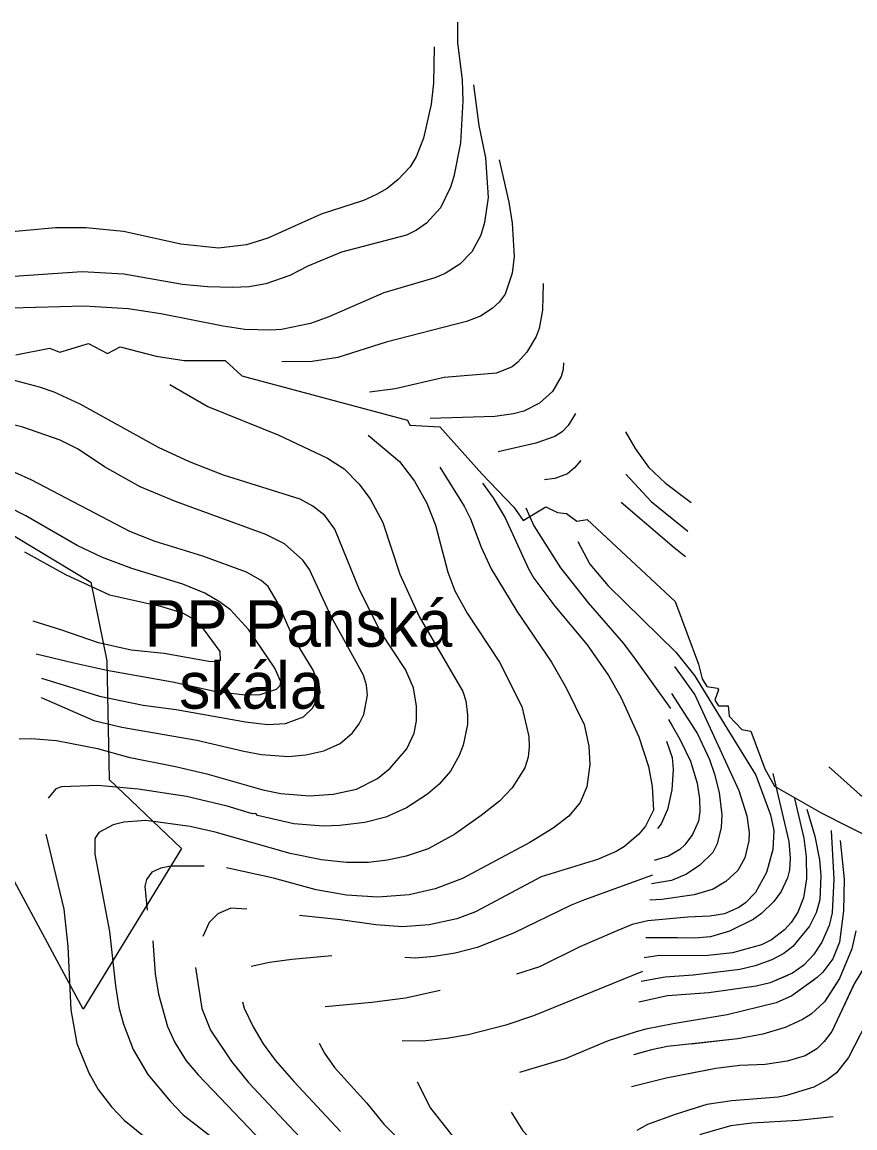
# Model space of a CAD drawing. Extents: x -1900516 to -575031, y -3809306 to -1157387.
# Drawn here: x -579489 to -579042, y -1158848 to -1158254 of the extents above; entities that cross this region are included whole.
import ezdxf

# ---------------------------------------------------------------- set-up
doc = ezdxf.new("R2010")
doc.units = 0
for name, color, linetype in [('01_SPRÁV_HRANICE', 7, 'Continuous'), ('01_VRSTEVNICE', 7, 'Continuous'), ('06_CHR_ÚZEMÍ', 7, 'Continuous')]:
    doc.layers.add(name, color=color, linetype=linetype)

msp = doc.modelspace()

# ---------------------------------------------------------------- linework, layer by layer
at = {"layer": '01_SPRÁV_HRANICE'}
for p, q in [((-579492.52, -1158432.42), (-579474.34, -1158428.74)), ((-579492.52, -1158432.42), (-579474.34, -1158428.74)), ((-579474.34, -1158428.74), (-579468.76, -1158430.87)), ((-579474.34, -1158428.74), (-579468.76, -1158430.87)), ((-579468.76, -1158430.87), (-579453.44, -1158426.35)), ((-579468.76, -1158430.87), (-579453.44, -1158426.35)), ((-579453.44, -1158426.35), (-579443.27, -1158431.59)), ((-579453.44, -1158426.35), (-579443.27, -1158431.59)), ((-579443.27, -1158431.59), (-579436.46, -1158428.12)), ((-579443.27, -1158431.59), (-579436.46, -1158428.12)), ((-579436.46, -1158428.12), (-579417.04, -1158433.06)), ((-579436.46, -1158428.12), (-579417.04, -1158433.06)), ((-579417.04, -1158433.06), (-579402.05, -1158435.39)), ((-579417.04, -1158433.06), (-579402.05, -1158435.39)), ((-579402.05, -1158435.39), (-579380.03, -1158435.41)), ((-579402.05, -1158435.39), (-579380.03, -1158435.41)), ((-579380.03, -1158435.41), (-579370.96, -1158443.7)), ((-579380.03, -1158435.41), (-579370.96, -1158443.7)), ((-579370.96, -1158443.7), (-579282.01, -1158467.49)), ((-579370.96, -1158443.7), (-579282.01, -1158467.49)), ((-579282.01, -1158467.49), (-579280.84, -1158470.22)), ((-579282.01, -1158467.49), (-579280.84, -1158470.22)), ((-579280.84, -1158470.22), (-579264.65, -1158471.08)), ((-579280.84, -1158470.22), (-579264.65, -1158471.08)), ((-579264.65, -1158471.08), (-579242.12, -1158496.25)), ((-579264.65, -1158471.08), (-579242.12, -1158496.25)), ((-579242.12, -1158496.25), (-579224.83, -1158514.13)), ((-579242.12, -1158496.25), (-579224.83, -1158514.13)), ((-579224.83, -1158514.13), (-579219.83, -1158521.43)), ((-579224.83, -1158514.13), (-579219.83, -1158521.43)), ((-579219.83, -1158521.43), (-579207.65, -1158514.05)), ((-579219.83, -1158521.43), (-579207.65, -1158514.05)), ((-579207.65, -1158514.05), (-579201.49, -1158517.14)), ((-579207.65, -1158514.05), (-579201.49, -1158517.14)), ((-579201.49, -1158517.14), (-579196.53, -1158517.67)), ((-579201.49, -1158517.14), (-579196.53, -1158517.67)), ((-579196.53, -1158517.67), (-579191.1, -1158521.77)), ((-579196.53, -1158517.67), (-579191.1, -1158521.77)), ((-579191.1, -1158521.77), (-579185.48, -1158520.78)), ((-579191.1, -1158521.77), (-579185.48, -1158520.78)), ((-579185.48, -1158520.78), (-579138.21, -1158564.86)), ((-579185.48, -1158520.78), (-579138.21, -1158564.86)), ((-579138.21, -1158564.86), (-579125.72, -1158598.51)), ((-579138.21, -1158564.86), (-579125.72, -1158598.51)), ((-579125.72, -1158598.51), (-579123.73, -1158606.52)), ((-579125.72, -1158598.51), (-579123.73, -1158606.52)), ((-579123.73, -1158606.52), (-579121.23, -1158610.56)), ((-579123.73, -1158606.52), (-579121.23, -1158610.56)), ((-579121.23, -1158610.56), (-579115.4, -1158611.53)), ((-579121.23, -1158610.56), (-579115.4, -1158611.53)), ((-579114.88, -1158612.44), (-579116.81, -1158617.88)), ((-579114.88, -1158612.44), (-579116.81, -1158617.88)), ((-579115.4, -1158611.53), (-579114.88, -1158612.44)), ((-579115.4, -1158611.53), (-579114.88, -1158612.44)), ((-579116.81, -1158617.88), (-579115, -1158620.98)), ((-579116.81, -1158617.88), (-579115, -1158620.98)), ((-579115, -1158620.98), (-579109.76, -1158620.86)), ((-579115, -1158620.98), (-579109.76, -1158620.86)), ((-579109.76, -1158620.86), (-579109.15, -1158626.56)), ((-579109.76, -1158620.86), (-579109.15, -1158626.56)), ((-579109.15, -1158626.56), (-579102.35, -1158633.68)), ((-579109.15, -1158626.56), (-579102.35, -1158633.68)), ((-579102.35, -1158633.68), (-579097.52, -1158634.56)), ((-579102.35, -1158633.68), (-579097.52, -1158634.56)), ((-579097.52, -1158634.56), (-579090.03, -1158654.79)), ((-579097.52, -1158634.56), (-579090.03, -1158654.79)), ((-579090.03, -1158654.79), (-579084.84, -1158664.04)), ((-579090.03, -1158654.79), (-579084.84, -1158664.04)), ((-579084.84, -1158664.04), (-579059.76, -1158678.42)), ((-579084.84, -1158664.04), (-579059.76, -1158678.42)), ((-579059.76, -1158678.42), (-579030.73, -1158693.13)), ((-579059.76, -1158678.42), (-579030.73, -1158693.13))]:
    msp.add_line(p, q, dxfattribs=at)
at = {"layer": '01_VRSTEVNICE'}
for p, q in [((-579267.78, -1158267), (-579268.06, -1158286.47)), ((-579268.06, -1158286.47), (-579269.32, -1158297.68)), ((-579269.32, -1158297.68), (-579273.38, -1158315.9)), ((-579273.38, -1158315.9), (-579277.31, -1158325.99)), ((-579277.31, -1158325.99), (-579280.67, -1158331.31)), ((-579280.67, -1158331.31), (-579287.11, -1158338.18)), ((-579293, -1158342.94), (-579298.6, -1158346.31)), ((-579287.11, -1158338.18), (-579293, -1158342.94)), ((-579298.6, -1158346.31), (-579305.75, -1158349.39)), ((-579305.75, -1158349.39), (-579328.45, -1158356.82)), ((-579328.45, -1158356.82), (-579357.04, -1158369.71)), ((-579471.1, -1158364.1), (-579509.78, -1158367.75)), ((-579454.85, -1158364.1), (-579471.1, -1158364.1)), ((-579434.67, -1158366.21), (-579454.85, -1158364.1)), ((-579403.84, -1158372.93), (-579434.67, -1158366.21)), ((-579357.04, -1158369.71), (-579368.53, -1158373.35)), ((-579383.66, -1158375.03), (-579403.84, -1158372.93)), ((-579368.53, -1158373.35), (-579383.66, -1158375.03))]:
    msp.add_line(p, q, dxfattribs=at)
for points in [[(-579255.17, -1158253.64), (-579255.17, -1158264.66), (-579252.64, -1158284.79), (-579252.36, -1158296), (-579253.62, -1158318.42), (-579257.13, -1158336.64), (-579258.95, -1158342.24), (-579264.27, -1158353.45), (-579271.84, -1158361.58), (-579277.17, -1158365.36), (-579282.49, -1158368.03), (-579317.45, -1158377.17), (-579335.59, -1158384.81), (-579345.22, -1158389.73), (-579358.16, -1158394.23), (-579367.13, -1158395.77), (-579376.09, -1158396.19), (-579389.55, -1158395.77), (-579403, -1158394.51), (-579434.39, -1158389.05), (-579456.81, -1158387.78), (-579501.65, -1158390.87)], [(-579246.57, -1158287.28), (-579243.68, -1158309.17), (-579240.17, -1158326.55), (-579238.63, -1158347.85), (-579240.59, -1158361.3), (-579242.69, -1158368.03), (-579247.46, -1158377), (-579253.91, -1158383.72), (-579261.75, -1158388.77), (-579267.36, -1158391.01), (-579294.82, -1158399), (-579324.25, -1158411.89), (-579334.06, -1158415.53), (-579349.75, -1158418.75), (-579355.64, -1158419.17), (-579369.37, -1158418.75), (-579381.14, -1158417.07), (-579414.49, -1158410.34), (-579432.15, -1158407.68), (-579455.69, -1158406.28), (-579494.92, -1158407.26), (-579522.39, -1158405.02), (-579542.01, -1158401.8), (-579571.56, -1158397.99)], [(-579232.69, -1158327.64), (-579227.56, -1158350.37), (-579225.74, -1158361.58), (-579224.76, -1158379.52), (-579225.74, -1158388.49), (-579229.52, -1158399.83), (-579232.75, -1158404.04), (-579236.53, -1158407.4), (-579242.83, -1158411.61), (-579250.26, -1158414.55), (-579293.42, -1158425.62), (-579319.48, -1158433.89), (-579333.22, -1158435.99), (-579349.58, -1158436.13)], [(-579209.15, -1158393.99), (-579209.48, -1158408.38), (-579211.31, -1158418.19), (-579212.85, -1158422.54), (-579217.89, -1158430.94), (-579222.66, -1158436.41), (-579225.74, -1158438.79), (-579234.29, -1158442.29), (-579262.31, -1158444.54), (-579288.66, -1158450.7), (-579302.47, -1158452.46)], [(-579198.19, -1158436.68), (-579198.35, -1158440.35), (-579199.4, -1158443.98), (-579204.16, -1158452.1), (-579211.03, -1158458.27), (-579219.57, -1158462.61), (-579225.04, -1158464.15), (-579235.13, -1158465.55), (-579269.85, -1158466.56)], [(-579490.72, -1158638.75), (-579483.99, -1158638.47), (-579470.54, -1158639.59), (-579448.68, -1158643.79), (-579431.86, -1158648.56), (-579406.64, -1158653.46), (-579389.83, -1158657.53), (-579359.84, -1158666.07), (-579350.03, -1158668.04), (-579334.62, -1158669.3), (-579322.01, -1158668.46), (-579309.4, -1158665.66), (-579298.19, -1158660.05), (-579291.32, -1158654.45), (-579282.35, -1158644.08), (-579278.43, -1158635.67), (-579277.17, -1158628.94), (-579277.17, -1158621.09), (-579278.85, -1158611.29), (-579283.05, -1158601.48), (-579296.36, -1158581.3), (-579307.85, -1158558.6), (-579321.03, -1158525.95), (-579326.49, -1158518.66), (-579332.94, -1158513.76), (-579339.66, -1158509.98), (-579380.86, -1158496.94), (-579399.08, -1158489.8), (-579415.89, -1158482.09), (-579457.93, -1158458.97), (-579471.94, -1158452.52), (-579479.79, -1158449.72), (-579493.24, -1158446.22)], [(-579409.7, -1158448.39), (-579389.27, -1158460.09), (-579351.15, -1158475.5), (-579325.09, -1158487.98), (-579316.12, -1158493.58), (-579308.13, -1158501.71), (-579302.11, -1158509.83), (-579295.24, -1158522.45), (-579286.13, -1158550.19), (-579275.77, -1158572.89), (-579252.22, -1158613.25), (-579250.68, -1158618.29), (-579249.7, -1158625.86), (-579249.84, -1158630.9), (-579252.08, -1158642.11), (-579254.19, -1158647.72), (-579258.95, -1158656.13), (-579264.97, -1158662.99), (-579271.28, -1158668.46), (-579282.49, -1158675.74), (-579293.7, -1158680.79), (-579304.91, -1158683.59), (-579318.36, -1158685.27), (-579327.33, -1158685.55), (-579343.03, -1158684.29), (-579362.64, -1158679.81), (-579363.48, -1158678.83), (-579365.31, -1158678.97), (-579378.9, -1158674.9), (-579400.76, -1158669.72), (-579426.82, -1158665.79), (-579448.4, -1158663.69), (-579468.02, -1158664.39), (-579470.96, -1158665.52), (-579475.02, -1158670.56)], [(-579478.81, -1158616.47), (-579450.64, -1158628.8), (-579435.51, -1158632.45), (-579395.15, -1158639.31), (-579369.93, -1158645.34), (-579360.4, -1158647.02), (-579346.11, -1158648.14), (-579336.58, -1158647.3), (-579327.05, -1158645.2), (-579318.22, -1158641.13), (-579311.5, -1158635.39), (-579307.99, -1158630.62), (-579305.47, -1158625.58), (-579303.51, -1158615.21), (-579304.07, -1158609.89), (-579305.61, -1158604.56), (-579322.99, -1158572.89), (-579334.76, -1158547.67), (-579338.26, -1158542.62), (-579348.07, -1158533.94), (-579358.16, -1158528.89), (-579406.64, -1158511.24), (-579425.7, -1158503.25), (-579444.76, -1158492.6), (-579459.05, -1158483.07), (-579468.58, -1158478.17), (-579488.76, -1158471.3), (-579519.02, -1158463.87)], [(-579191.7, -1158463.81), (-579195.75, -1158470.32), (-579198.98, -1158473.68), (-579202.9, -1158476.34), (-579212.99, -1158479.85), (-579233.23, -1158484.51)], [(-579164.88, -1158473.8), (-579159.74, -1158482.65), (-579152.45, -1158492.74), (-579143.48, -1158501.29), (-579129.58, -1158511.7)], [(-579303.15, -1158475.59), (-579286.41, -1158489.66), (-579278.29, -1158500.17), (-579271.56, -1158512.08), (-579266.94, -1158523.85), (-579260.35, -1158549.07), (-579256.57, -1158559.16), (-579249.98, -1158571.21), (-579232.6, -1158597.55), (-579220.56, -1158621.38), (-579216.91, -1158637.35), (-579216.63, -1158642.96), (-579217.19, -1158648.56), (-579219.01, -1158654.17), (-579225.74, -1158664.95), (-579232.6, -1158672.1), (-579242.41, -1158679.95), (-579256.57, -1158689.9), (-579271, -1158697.74), (-579282.77, -1158701.67), (-579292.86, -1158703.91), (-579302.95, -1158705.03), (-579314.72, -1158705.17), (-579328.17, -1158703.77), (-579344.99, -1158700.27), (-579385.34, -1158688.78), (-579398.8, -1158685.69), (-579422.62, -1158682.61), (-579434.39, -1158683.45), (-579440.27, -1158684.85), (-579447.84, -1158689.06), (-579450.08, -1158692.28), (-579450.08, -1158700.69), (-579442.09, -1158742.16), (-579439.01, -1158771.31), (-579437.05, -1158782.8), (-579434.67, -1158792.05), (-579429.48, -1158805.5), (-579421.64, -1158818.95), (-579409.58, -1158833.39), (-579402.51, -1158840.62)], [(-579478.6, -1158606.12), (-579461.29, -1158611.43), (-579447.56, -1158615.77), (-579424.02, -1158620.67), (-579406.36, -1158622.92), (-579369.09, -1158629.5), (-579357.32, -1158631.04), (-579347.51, -1158630.48), (-579337.84, -1158626.84), (-579332.94, -1158621.94), (-579328.87, -1158613.81), (-579329.29, -1158610.73), (-579332.8, -1158601.76), (-579343.58, -1158583.82), (-579351.57, -1158565.89), (-579356.9, -1158556.92), (-579360.68, -1158553.55), (-579368.53, -1158549.21), (-579392.07, -1158540.52), (-579417.57, -1158532.68), (-579431.31, -1158527.35), (-579484.27, -1158499.47), (-579501.93, -1158491.62)], [(-579188.86, -1158489.06), (-579192.25, -1158493.02), (-579196.03, -1158496.24), (-579202.9, -1158498.9), (-579208.43, -1158499.52)], [(-579264.7, -1158492.74), (-579251.52, -1158513.76), (-579248.16, -1158520.48), (-579242.41, -1158535.62), (-579237.09, -1158547.39), (-579223.36, -1158570.09), (-579204.72, -1158597.55), (-579196.73, -1158611.29), (-579187.06, -1158630.9), (-579184.54, -1158642.68), (-579184.12, -1158652.48), (-579185.66, -1158664.53), (-579189.17, -1158672.94), (-579195.33, -1158680.23), (-579203.74, -1158686.67), (-579216.35, -1158694.38), (-579252.5, -1158713.72), (-579267.08, -1158719.32), (-579281.09, -1158722.41), (-579297.91, -1158723.81), (-579314.72, -1158722.69), (-579331.11, -1158719.74), (-579353.95, -1158713.58), (-579379.32, -1158707.97)], [(-579164.79, -1158496.43), (-579151.05, -1158511.1), (-579131.38, -1158527.13)], [(-579241.78, -1158501.41), (-579235.93, -1158509.26), (-579229.52, -1158519.92), (-579217.05, -1158547.39), (-579214.11, -1158552.43), (-579202.9, -1158567.43), (-579185.52, -1158588.17), (-579174.03, -1158604.7), (-579167.45, -1158616.33), (-579157.78, -1158637.63), (-579152.59, -1158653.6), (-579150.49, -1158664.25), (-579149.93, -1158677.01), (-579154.14, -1158685.55), (-579157.78, -1158689.9), (-579165.48, -1158696.48), (-579169.83, -1158699.15), (-579179.92, -1158703.49), (-579210.19, -1158712.88), (-579245.5, -1158731.66), (-579255.59, -1158735.44), (-579270.44, -1158738.66), (-579284.73, -1158739.64), (-579299.03, -1158738.66), (-579318.08, -1158735.86), (-579340.08, -1158733.62)], [(-579481.61, -1158593.07), (-579461.29, -1158597.83), (-579443.64, -1158601.76), (-579408.32, -1158608.06), (-579384.78, -1158613.25), (-579369.09, -1158615.07), (-579361.24, -1158614.79), (-579352.41, -1158611.99), (-579350.45, -1158610.03), (-579350.03, -1158608.06), (-579353.25, -1158600.64), (-579367.27, -1158580.04), (-579377.22, -1158569.39), (-579383.1, -1158565.04), (-579390.95, -1158560.42), (-579402.72, -1158555.66), (-579430.18, -1158547.11), (-579445.88, -1158541.22), (-579459.61, -1158534.78), (-579487.08, -1158518.8), (-579506.69, -1158508.99)], [(-579218.52, -1158514.53), (-579214.11, -1158524.27), (-579199.82, -1158546.83), (-579184.96, -1158565.6), (-579166.05, -1158587.47), (-579159.74, -1158595.87), (-579140.77, -1158622.45)], [(-579167.25, -1158511.59), (-579138.72, -1158535.9), (-579132.68, -1158540.77)], [(-579190.49, -1158532.73), (-579183.98, -1158544.87), (-579174.17, -1158556.5), (-579137.93, -1158592.03)], [(-579487.78, -1158538.14), (-579465.78, -1158550.47), (-579442.23, -1158561.26), (-579414.77, -1158567.43), (-579403, -1158570.93), (-579397.11, -1158574.15), (-579391.79, -1158579.62), (-579382.82, -1158591.67), (-579382.61, -1158596.51), (-579384.78, -1158597.35), (-579388.71, -1158597.13), (-579412.81, -1158592.79), (-579430.46, -1158591.11), (-579448.12, -1158587.04), (-579467.74, -1158580.32), (-579483.15, -1158575.55)], [(-579137.93, -1158592.03), (-579127.86, -1158604.62), (-579110.36, -1158632.87), (-579094.84, -1158658.27), (-579086.94, -1158679.43), (-579085.25, -1158687.9), (-579085.81, -1158698.06), (-579089.06, -1158710.47), (-579095.12, -1158721.2), (-579100.34, -1158726.7), (-579104.01, -1158729.24), (-579111.63, -1158732.62), (-579119.53, -1158733.89), (-579131.39, -1158734.46), (-579152.93, -1158736.45)], [(-579138.62, -1158599.86), (-579127.58, -1158615.09), (-579104.01, -1158666.45), (-579099.64, -1158680), (-579098.51, -1158689.03), (-579098.65, -1158693.54), (-579100.77, -1158702.57), (-579104.58, -1158709.34), (-579110.93, -1158715.41), (-579117.84, -1158719.36), (-579128, -1158722.47), (-579145.35, -1158725.01), (-579151.78, -1158725.35)], [(-579140.17, -1158614.3), (-579126.16, -1158635.98), (-579119.82, -1158649.8), (-579116.99, -1158657.7), (-579114.59, -1158667.58), (-579113.18, -1158679.43), (-579113.47, -1158686.34), (-579115.72, -1158695.09), (-579117.98, -1158699.75), (-579124.89, -1158706.52), (-579132.09, -1158711.32), (-579140.13, -1158714.71), (-579150.84, -1158716.57)], [(-579141.72, -1158628.26), (-579139.85, -1158631.74), (-579135.62, -1158638.8), (-579129.97, -1158650.65), (-579126.31, -1158662.5), (-579125.04, -1158670.97), (-579124.89, -1158677.74), (-579125.74, -1158682.96), (-579128.84, -1158690.16), (-579132.94, -1158695.66), (-579135.62, -1158698.06), (-579141.83, -1158701.73), (-579149.53, -1158704.09)], [(-579142.92, -1158640.01), (-579139.83, -1158648.68), (-579139.29, -1158655.16), (-579139.99, -1158666.03), (-579142.39, -1158676.61), (-579145.64, -1158684.37), (-579147.77, -1158686.88)], [(-579085.69, -1158657.26), (-579077.2, -1158693.82), (-579076.5, -1158702.71), (-579076.78, -1158709.06), (-579077.77, -1158713.29), (-579081.3, -1158720.77), (-579085.25, -1158726.13), (-579091.74, -1158732.48), (-579096.25, -1158735.73), (-579109.09, -1158742.08), (-579119.25, -1158745.04), (-579127.72, -1158745.75), (-579137.03, -1158745.6), (-579154, -1158745.67)], [(-579055.62, -1158653.75), (-579050.96, -1158657.84), (-579038.83, -1158668.71), (-579026.13, -1158676.33), (-579015.97, -1158680.84), (-579000.73, -1158685.07), (-578978.72, -1158688.6), (-578953.33, -1158694.1), (-578912.69, -1158708.36), (-578866.41, -1158720.91), (-578858.94, -1158723.74)], [(-579074.05, -1158670.71), (-579069.02, -1158692.13), (-579067.75, -1158702.01), (-579067.61, -1158713.86), (-579069.3, -1158724.02), (-579072.27, -1158731.78), (-579075.94, -1158737.42), (-579079.46, -1158741.23), (-579086.52, -1158746.73), (-579091.88, -1158749.27), (-579107.4, -1158753.65), (-579122.35, -1158755.2), (-579146.64, -1158755.16), (-579154.85, -1158756.29)], [(-579067.49, -1158676.5), (-579063.24, -1158691), (-579060.7, -1158703.7), (-579059.85, -1158712.17), (-579060.42, -1158725.15), (-579062.39, -1158732.2), (-579066.06, -1158739.26), (-579074.95, -1158750.26), (-579079.74, -1158754.07), (-579086.23, -1158757.46), (-579095.27, -1158760.56), (-579103.45, -1158762.53), (-579128.56, -1158765.64), (-579143.53, -1158766.77), (-579156.54, -1158769.03)], [(-579476.43, -1158689.9), (-579466.62, -1158730.25), (-579464.51, -1158750.29), (-579462.97, -1158784.2), (-579459.75, -1158802.42), (-579453.3, -1158818.11), (-579448.26, -1158827.08), (-579441.1, -1158836.33)], [(-579049.54, -1158693.33), (-579047.44, -1158714.14), (-579047.72, -1158731.07), (-579049.97, -1158748), (-579053.5, -1158756.89), (-579058.86, -1158763.95), (-579061.97, -1158766.91), (-579075.51, -1158776.79), (-579083.98, -1158780.59), (-579110.22, -1158786.95), (-579139.32, -1158791.82), (-579154.04, -1158794.65), (-579159.15, -1158796)], [(-579054.38, -1158687.98), (-579052.94, -1158714.14), (-579053.78, -1158732.2), (-579055.48, -1158738.97), (-579059.43, -1158748), (-579063.8, -1158754.78), (-579069.02, -1158760.28), (-579075.23, -1158764.65), (-579087.08, -1158769.73), (-579094.7, -1158771.56), (-579120.1, -1158775.09), (-579142.4, -1158776.68), (-579157.68, -1158780.07)], [(-579391.37, -1158707.13), (-579409.45, -1158707.13), (-579414.49, -1158708.11), (-579419.39, -1158710.22), (-579422.2, -1158714.28), (-579423.18, -1158717.78), (-579421.99, -1158730.76)], [(-579150.4, -1158711.9), (-579186.93, -1158725.21), (-579194.07, -1158728.01), (-579225.04, -1158743.15), (-579244.66, -1158750.71), (-579256.43, -1158753.79), (-579267.64, -1158755.62), (-579277.73, -1158756.46), (-579283.47, -1158756.18)], [(-579368.39, -1158730.11), (-579376.96, -1158729.6), (-579383.87, -1158732.78), (-579388.51, -1158737.28), (-579391.96, -1158744.86)], [(-579152.93, -1158736.45), (-579161.34, -1158738.49), (-579171.09, -1158742.58), (-579189.45, -1158750.43), (-579211.03, -1158761.22), (-579223.5, -1158765.15)], [(-579041.08, -1158741.79), (-579043.2, -1158751.53), (-579049.83, -1158767.47), (-579057.88, -1158780.03), (-579065.07, -1158786.52), (-579069.87, -1158789.48), (-579079.18, -1158793.72), (-579091.03, -1158797.39), (-579104.58, -1158799.93), (-579142.25, -1158804.02), (-579150.86, -1158805.71), (-579160.59, -1158808.53)], [(-579418.81, -1158747.12), (-579417.61, -1158764.92), (-579415.75, -1158775.79), (-579410.99, -1158793.17), (-579407.06, -1158801.86), (-579400.9, -1158811.67), (-579394.59, -1158819.23), (-579371.1, -1158843.77)], [(-579322.71, -1158755.34), (-579344.15, -1158757.16), (-579356.2, -1158758.84), (-579366.05, -1158760.96)], [(-579034.31, -1158757.6), (-579042.07, -1158770.3), (-579054.07, -1158795.83), (-579058.16, -1158801.34), (-579062.11, -1158805.15), (-579068.32, -1158808.96), (-579078.05, -1158811.78), (-579089.9, -1158813.61), (-579103.45, -1158814.18), (-579116.43, -1158815.73), (-579143.09, -1158820.95), (-579161.72, -1158825.6)], [(-579395.89, -1158761.51), (-579392.49, -1158783.64), (-579387.87, -1158795.13), (-579376.66, -1158811.95), (-579367.41, -1158823.3), (-579345.57, -1158846.59)], [(-579155.83, -1158763.73), (-579214.39, -1158787.43), (-579229.24, -1158792.47), (-579249.42, -1158797.65), (-579261.05, -1158799.62), (-579273.8, -1158801.02), (-579284.95, -1158800.85)], [(-579051.32, -1158769.79), (-579057.88, -1158780.03), (-579065.07, -1158786.52), (-579069.87, -1158789.48), (-579079.18, -1158793.72), (-579091.03, -1158797.39), (-579104.58, -1158799.93), (-579129.61, -1158802.64)], [(-579063.4, -1158767.95), (-579075.51, -1158776.79), (-579083.98, -1158780.59), (-579110.22, -1158786.95), (-579128.57, -1158790.02)], [(-579077.82, -1158765.76), (-579087.08, -1158769.73), (-579094.7, -1158771.56), (-579120.1, -1158775.09), (-579127.39, -1158775.61)], [(-579264.41, -1158773.83), (-579283.05, -1158778.04), (-579301.27, -1158780.28), (-579326.25, -1158782.66)], [(-579024.3, -1158773.89), (-579032.34, -1158785.25), (-579045.04, -1158809.8), (-579051.53, -1158818.13), (-579056.61, -1158821.94), (-579063.66, -1158825.75), (-579078.33, -1158830.26), (-579082.85, -1158831.11), (-579107.68, -1158833.08), (-579121.23, -1158835.06), (-579132.58, -1158838.66)], [(-579042.47, -1158771.13), (-579054.07, -1158795.83), (-579058.16, -1158801.34), (-579062.11, -1158805.15), (-579068.32, -1158808.96), (-579078.05, -1158811.78), (-579089.9, -1158813.61), (-579103.45, -1158814.18), (-579116.43, -1158815.73), (-579130.93, -1158818.57)], [(-579042.47, -1158771.13), (-579054.07, -1158795.83), (-579058.16, -1158801.34), (-579062.11, -1158805.15), (-579068.32, -1158808.96), (-579078.05, -1158811.78), (-579089.9, -1158813.61), (-579103.45, -1158814.18), (-579116.43, -1158815.73), (-579130.93, -1158818.57)], [(-579370.74, -1158779.88), (-579369.74, -1158783.38), (-579365.03, -1158793.45), (-579359.56, -1158802.56), (-579353.11, -1158811.25), (-579343.17, -1158822.74), (-579318.02, -1158849.58)], [(-579032.34, -1158785.25), (-579045.04, -1158809.8), (-579051.53, -1158818.13), (-579056.61, -1158821.94), (-579063.66, -1158825.75), (-579078.33, -1158830.26), (-579082.85, -1158831.11), (-579107.68, -1158833.08), (-579121.23, -1158835.06), (-579138.22, -1158840.45), (-579153.11, -1158845.92), (-579158.76, -1158849.17)], [(-579159.15, -1158796), (-579174.13, -1158800.93), (-579197.29, -1158810.54), (-579221.85, -1158817.85)], [(-579329.43, -1158802.22), (-579326.63, -1158807.6), (-579321.31, -1158815.17), (-579303.93, -1158834.37), (-579294.78, -1158845.63), (-579287.9, -1158852.53)], [(-579276.92, -1158823.01), (-579269.6, -1158837.17), (-579258.95, -1158850.62), (-579252.5, -1158856.47)], [(-579441.1, -1158836.33), (-579434.25, -1158843.63), (-579423.9, -1158851.88)], [(-579402.51, -1158840.62), (-579368.22, -1158867.41)], [(-579226.38, -1158839.22), (-579220.13, -1158849.22), (-579213.65, -1158856.02), (-579207.5, -1158861.3)], [(-579053.36, -1158841.69), (-579072.13, -1158843.8), (-579096.96, -1158845.07), (-579108.25, -1158846.63), (-579124.05, -1158851), (-579132.66, -1158855.94), (-579136.07, -1158858), (-579137.77, -1158859.7), (-579138.33, -1158861.83), (-579136.78, -1158864.94), (-579131.03, -1158869.4)], [(-579053.36, -1158841.69), (-579072.13, -1158843.8), (-579096.96, -1158845.07), (-579108.25, -1158846.63), (-579124.05, -1158851), (-579132.66, -1158855.94), (-579134.08, -1158856.8)], [(-579053.36, -1158841.69), (-579072.13, -1158843.8), (-579096.96, -1158845.07), (-579108.25, -1158846.63), (-579124.05, -1158851), (-579132.66, -1158855.94), (-579134.08, -1158856.8)], [(-579371.1, -1158843.77), (-579349.85, -1158865.97)], [(-579345.57, -1158846.59), (-579339.54, -1158853)]]:
    msp.add_lwpolyline(points, dxfattribs=at)
at = {"layer": '06_CHR_ÚZEMÍ'}
for p, q in [((-579546.34, -1158497.86), (-579452.14, -1158554.47)), ((-579452.14, -1158554.47), (-579443.63, -1158596.8)), ((-579443.63, -1158596.8), (-579442.25, -1158660.55)), ((-579442.25, -1158660.55), (-579403.53, -1158697.65)), ((-579456.26, -1158783.95), (-579502.4, -1158698.75)), ((-579403.53, -1158697.65), (-579456.26, -1158783.95))]:
    msp.add_line(p, q, dxfattribs=at)

# ---------------------------------------------------------------- texts
for s, p in [('PP Panská', (-579423.28, -1158589.2)), ('  skála', (-579423.28, -1158622.47))]:
    msp.add_text(s, height=25, dxfattribs=at).set_placement(p)

doc.saveas('drawing.dxf')
